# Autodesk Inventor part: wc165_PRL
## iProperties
Shininess: 64.0
Length Units: 11272
Angle Units: 11279
Time Units: 11290
Mass Units: 11286
Length Display Precision: 3
Angle Display Precision: 2
Compacted: True
Part Number: wc165_PRL
Document SubType Name: Modeling
Created: 2004-08
Designer: John Blackburn
Manufacturer: Standard
Standards Organization: Custom
Material: Phenolic
Density: 0.0
Volumn: 0.0
Area: 0.0
PropertySet Name: Model Information
Control State: 0
Master: False
Checked Out: False
Author: John Blackburn
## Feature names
1. Revolution1
